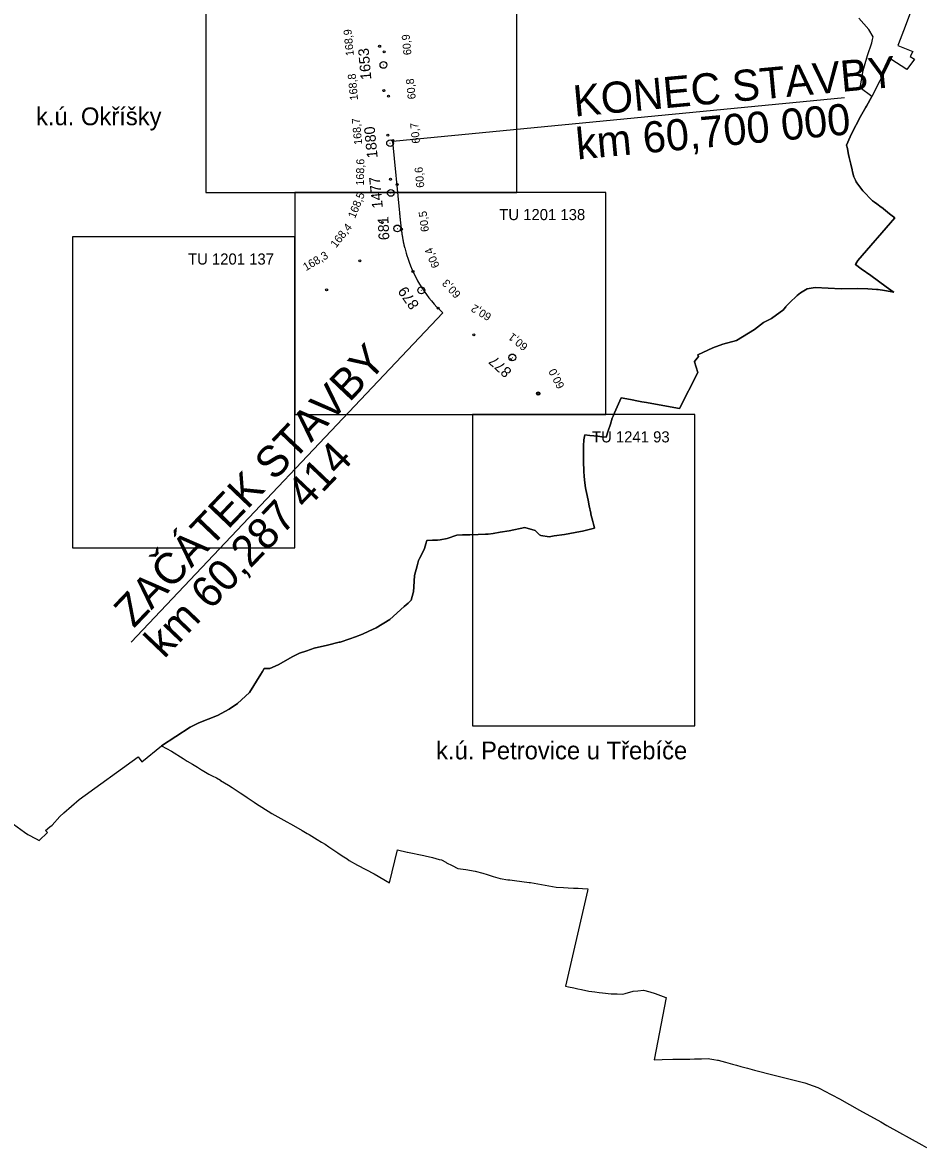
# Model space of a CAD drawing. Extents: x -661028 to -488604, y -1150850 to -1117549.
# Drawn here: x -659612 to -657588, y -1150849 to -1148318 of the extents above; entities that cross this region are included whole.
import ezdxf

# ---------------------------------------------------------------- set-up
doc = ezdxf.new("R2010")
doc.units = 0
for name, color, linetype in [('Polygon ku', 7, 'Continuous'), ('Pop  PČ popisy', 7, 'Continuous'), ('Ramecky', 7, 'Continuous'), ('Vrstva 7', 7, 'Continuous'), ('Značky bodu BP', 7, 'Continuous'), ('ŽBP', 7, 'Continuous')]:
    doc.layers.add(name, color=color, linetype=linetype)

msp = doc.modelspace()

# ---------------------------------------------------------------- linework, layer by layer
at = {"layer": 'Polygon ku'}
for points in [[(-657576.5, -1148192.9), (-657630.8, -1148336.7), (-657641.9, -1148366), (-657643.3, -1148369.6), (-657609.7, -1148383.3), (-657615.4, -1148394.8), (-657605.9, -1148400.4), (-657623, -1148423.5), (-657659.5, -1148400.5), (-657661.2, -1148404), (-657665.6, -1148413.6), (-657702.1, -1148484.7), (-657714, -1148506.4), (-657715.2, -1148508.4), (-657727.1, -1148529.4), (-657747.4, -1148568.7), (-657750.8, -1148575.3), (-657758.6, -1148593.8), (-657756.6, -1148601.7), (-657755.6, -1148607), (-657754.1, -1148614.6), (-657752.7, -1148621.8), (-657749.3, -1148636.7), (-657746.3, -1148649.5), (-657745.3, -1148654.1), (-657742.8, -1148664.9), (-657739, -1148672.4), (-657736.9, -1148676.7), (-657735.6, -1148678.9), (-657721.9, -1148696.4), (-657700.4, -1148719), (-657696.2, -1148722.1), (-657690.6, -1148726.1), (-657681, -1148733), (-657679.5, -1148734), (-657676.6, -1148736.4), (-657675.4, -1148737.3), (-657671.3, -1148740.6), (-657662.1, -1148748), (-657656.3, -1148752.8), (-657650.4, -1148757.5), (-657733.3, -1148853.6), (-657735.7, -1148856.8), (-657738.3, -1148860.6), (-657739, -1148861.8), (-657738.4, -1148862.3), (-657725.8, -1148871.9), (-657704.1, -1148887.4), (-657669.5, -1148912.2), (-657659, -1148919.7), (-657652.8, -1148924.8), (-657673.3, -1148921.1), (-657687.8, -1148918.5), (-657691.2, -1148918.3), (-657711.3, -1148917.4), (-657733.4, -1148916.4), (-657770.7, -1148916.9), (-657829.3, -1148913.9), (-657847.4, -1148917.4), (-657862.2, -1148925.7), (-657869.7, -1148931.8), (-657887, -1148948.8), (-657891.3, -1148953), (-657895.2, -1148956.8), (-657895.6, -1148957.3), (-657899.5, -1148962.5), (-657900.2, -1148963.5), (-657927.6, -1148984), (-657945.9, -1148992.9), (-657965.7, -1149008.8), (-658006.1, -1149033.2), (-658036.8, -1149041.4), (-658059.4, -1149049.8), (-658093.4, -1149065.5), (-658091.5, -1149069.6), (-658101, -1149080.2), (-658100.7, -1149081.3), (-658093, -1149105.1), (-658134.7, -1149186.5), (-658155.6, -1149182.6), (-658175.8, -1149178.9), (-658196.5, -1149175.1), (-658209, -1149172.8), (-658218.9, -1149170.9), (-658230.4, -1149168.8), (-658240.9, -1149166.9), (-658252.7, -1149164.7), (-658265.7, -1149162.3), (-658280.6, -1149195.8), (-658283.8, -1149203.2), (-658285.6, -1149208.3), (-658289.9, -1149221.3), (-658295.1, -1149236.5), (-658299.8, -1149250.7), (-658309.5, -1149249.6), (-658318.1, -1149248.7), (-658327, -1149247.7), (-658336.4, -1149246.7), (-658347.4, -1149245.5), (-658350, -1149256.9), (-658350.1, -1149270.3), (-658350.2, -1149274), (-658350.4, -1149293.6), (-658350.5, -1149304.8), (-658349.4, -1149328.3), (-658348.9, -1149338.6), (-658348.8, -1149339.1), (-658347.1, -1149353.2), (-658345.8, -1149364.4), (-658345.3, -1149368.6), (-658343.9, -1149375.4), (-658340.3, -1149392.6), (-658337.6, -1149405.5), (-658334.3, -1149421.5), (-658333.8, -1149423.9), (-658329.4, -1149440.5), (-658327.7, -1149446.6), (-658326.3, -1149451.9), (-658325.4, -1149455.3), (-658352.6, -1149461.9), (-658357.5, -1149463.1), (-658393.3, -1149469.6), (-658416.2, -1149473), (-658427.9, -1149474.8), (-658446.3, -1149471.6), (-658449.6, -1149470.2), (-658455.7, -1149464.3), (-658459.4, -1149460.8), (-658482.5, -1149453.9), (-658517.9, -1149461.1), (-658537.7, -1149464.5), (-658553.8, -1149467.2), (-658565.1, -1149468.6), (-658571.2, -1149468.8), (-658587.6, -1149469.4), (-658606.4, -1149470.1), (-658622.8, -1149470.7), (-658635.2, -1149471.2), (-658657.4, -1149478.9), (-658672.5, -1149481.3), (-658678.6, -1149482.3), (-658690.2, -1149482.5), (-658702.7, -1149482.8), (-658704.7, -1149490.4), (-658707.7, -1149501.1), (-658712.8, -1149511.1), (-658719, -1149523.3), (-658721.4, -1149527.8), (-658724.6, -1149540.2), (-658730.2, -1149561.8), (-658731.9, -1149587.5), (-658732.6, -1149598.3), (-658733.3, -1149601.1), (-658735.5, -1149609.2), (-658737.7, -1149617.4), (-658742.4, -1149621.6), (-658744.9, -1149623.9), (-658753.4, -1149631.5), (-658785.8, -1149660.5), (-658816.8, -1149679.7), (-658833, -1149687.3), (-658847.6, -1149694.1), (-658862.9, -1149699.5), (-658876, -1149704.1), (-658878.5, -1149704.9), (-658895.6, -1149710.9), (-658898, -1149711.8), (-658899.9, -1149712.2), (-658926.3, -1149718.6), (-658956.1, -1149725.7), (-658973, -1149731.2), (-658989, -1149736.5), (-659005.7, -1149744.9), (-659035.7, -1149762.3), (-659050.7, -1149768.8), (-659055.6, -1149771), (-659068.6, -1149770.9), (-659072.6, -1149778.1), (-659075.8, -1149784.1), (-659101.6, -1149824.7), (-659128.3, -1149849.9), (-659147.4, -1149862.7), (-659173.9, -1149877.1), (-659215.5, -1149893.2), (-659216.8, -1149893.7), (-659234.9, -1149903.1), (-659299.6, -1149945.1), (-659277.3, -1149957.1), (-659250.9, -1149973.4), (-659241.5, -1149979.2), (-659230.1, -1149986.2), (-659218.5, -1149993.3), (-659209.6, -1149998.7), (-659208.4, -1149999.4), (-659192.7, -1150008.4), (-659185.3, -1150012.4), (-659176.2, -1150017.2), (-659167.2, -1150022.4), (-659166.6, -1150022.8), (-659158.2, -1150028), (-659149, -1150033.7), (-659140.6, -1150038.9), (-659122.8, -1150050.4), (-659110.1, -1150059), (-659107, -1150061.1), (-659091.4, -1150071.8), (-659088, -1150074), (-659051.2, -1150096.9), (-659038.2, -1150105), (-659024.2, -1150112.4), (-659002.7, -1150123.9), (-658983.5, -1150135.3), (-658972.2, -1150141.9), (-658967.3, -1150144.8), (-658961.6, -1150148.4), (-658949.2, -1150156.1), (-658939.9, -1150161.6), (-658931.8, -1150166.4), (-658923, -1150172.3), (-658903.3, -1150185.5), (-658893.2, -1150192.2), (-658882.1, -1150199.5), (-658877.3, -1150202.7), (-658859, -1150213.3), (-658821, -1150233), (-658787.1, -1150253.3), (-658768.4, -1150178.8), (-658746.7, -1150183.9), (-658746.2, -1150184), (-658709.3, -1150191.5), (-658706.3, -1150192.3), (-658690.2, -1150196.5), (-658674.9, -1150200.5), (-658670.1, -1150201.8), (-658660, -1150206.9), (-658658.2, -1150207.9), (-658645.7, -1150214.1), (-658632.8, -1150220.6), (-658615.2, -1150223.4), (-658594.2, -1150226.6), (-658577.1, -1150231.2), (-658567.3, -1150234.3), (-658558.4, -1150237.1), (-658553.4, -1150238.7), (-658537.7, -1150243.8), (-658520.7, -1150246.1), (-658516.2, -1150246.7), (-658505.4, -1150248), (-658489, -1150250.1), (-658472.3, -1150252.1), (-658469.5, -1150252.5), (-658412, -1150263.3), (-658395.5, -1150264), (-658384.6, -1150264.5), (-658373.2, -1150265), (-658362.4, -1150265.4), (-658352.8, -1150265.9), (-658340.6, -1150266.4), (-658341.7, -1150271.4), (-658391, -1150485.6), (-658384.4, -1150487), (-658371.9, -1150489.7), (-658362.9, -1150491.7), (-658355.2, -1150493.3), (-658338.6, -1150496.9), (-658324.9, -1150498.6), (-658314.9, -1150499.8), (-658307.6, -1150500.6), (-658287.9, -1150502.6), (-658274.4, -1150503.2), (-658262.5, -1150503.8), (-658256.5, -1150502.1), (-658238.4, -1150497.2), (-658228.2, -1150496), (-658215.8, -1150494.5), (-658201.2, -1150498.6), (-658189.3, -1150502), (-658183.6, -1150504.1), (-658165.5, -1150510.9), (-658164.2, -1150511.4), (-658191.6, -1150651), (-658173.4, -1150650.6), (-658149.3, -1150650.2), (-658145.1, -1150650.1), (-658118, -1150649.6), (-658111.5, -1150649.5), (-658100.5, -1150649.2), (-658098.2, -1150649.2), (-658084.8, -1150648.9), (-658069.6, -1150648.7), (-658066.1, -1150649.1), (-658057.3, -1150650.3), (-658049.4, -1150651.8), (-658047.7, -1150652.3), (-658031, -1150656.8), (-658015.2, -1150661), (-658006.2, -1150663.4), (-657996.3, -1150666.1), (-657981.6, -1150670), (-657965.5, -1150674.4), (-657921.9, -1150686.1), (-657853, -1150702.8), (-657834.2, -1150709.6), (-657823.4, -1150713.8), (-657817.3, -1150716.6), (-657809, -1150721.3), (-657774.5, -1150739.2), (-657729.7, -1150764.3), (-657682, -1150791), (-657668.2, -1150798.7), (-657589.5, -1150842.6), (-657579, -1150848.5)], [(-659632.5, -1150121.5), (-659607.3, -1150139.4), (-659599.8, -1150144.7), (-659581.1, -1150154.6), (-659574.4, -1150158.1), (-659555.9, -1150140), (-659560.1, -1150135.4), (-659550.8, -1150127.6), (-659545.7, -1150123.5), (-659528.3, -1150103.9), (-659519.2, -1150095.5), (-659484.9, -1150066), (-659351.8, -1149969.8), (-659344, -1149980.7), (-659299.6, -1149945.1), (-659234.9, -1149903.1), (-659216.8, -1149893.7), (-659215.5, -1149893.2), (-659173.9, -1149877.1), (-659147.4, -1149862.7), (-659128.3, -1149849.9), (-659101.6, -1149824.7), (-659075.8, -1149784.1), (-659072.6, -1149778.1), (-659068.6, -1149770.9), (-659055.6, -1149771), (-659050.7, -1149768.8), (-659035.7, -1149762.3), (-659005.7, -1149744.9), (-658989, -1149736.5), (-658973, -1149731.2), (-658956.1, -1149725.7), (-658926.3, -1149718.6), (-658899.9, -1149712.2), (-658898, -1149711.8), (-658895.6, -1149710.9), (-658878.5, -1149704.9), (-658876, -1149704.1), (-658862.9, -1149699.5), (-658847.6, -1149694.1), (-658833, -1149687.3), (-658816.8, -1149679.7), (-658785.8, -1149660.5), (-658753.4, -1149631.5), (-658744.9, -1149623.9), (-658742.4, -1149621.6), (-658737.7, -1149617.4), (-658735.5, -1149609.2), (-658733.3, -1149601.1), (-658732.6, -1149598.3), (-658731.9, -1149587.5), (-658730.2, -1149561.8), (-658724.6, -1149540.2), (-658721.4, -1149527.8), (-658719, -1149523.3), (-658712.8, -1149511.1), (-658707.7, -1149501.1), (-658704.7, -1149490.4), (-658702.7, -1149482.8), (-658690.2, -1149482.5), (-658678.6, -1149482.3), (-658672.5, -1149481.3), (-658657.4, -1149478.9), (-658635.2, -1149471.2), (-658622.8, -1149470.7), (-658606.4, -1149470.1), (-658587.6, -1149469.4), (-658571.2, -1149468.8), (-658565.1, -1149468.6), (-658553.8, -1149467.2), (-658537.7, -1149464.5), (-658517.9, -1149461.1), (-658482.5, -1149453.9), (-658459.4, -1149460.8), (-658455.7, -1149464.3), (-658449.6, -1149470.2), (-658446.3, -1149471.6), (-658427.9, -1149474.8), (-658416.2, -1149473), (-658393.3, -1149469.6), (-658357.5, -1149463.1), (-658352.6, -1149461.9), (-658325.4, -1149455.3), (-658326.3, -1149451.9), (-658327.7, -1149446.6), (-658329.4, -1149440.5), (-658333.8, -1149423.9), (-658334.3, -1149421.5), (-658337.6, -1149405.5), (-658340.3, -1149392.6), (-658343.9, -1149375.4), (-658345.3, -1149368.6), (-658345.8, -1149364.4), (-658347.1, -1149353.2), (-658348.8, -1149339.1), (-658348.9, -1149338.6), (-658349.4, -1149328.3), (-658350.5, -1149304.8), (-658350.4, -1149293.6), (-658350.2, -1149274), (-658350.1, -1149270.3), (-658350, -1149256.9), (-658347.4, -1149245.5), (-658336.4, -1149246.7), (-658327, -1149247.7), (-658318.1, -1149248.7), (-658309.5, -1149249.6), (-658299.8, -1149250.7), (-658295.1, -1149236.5), (-658289.9, -1149221.3), (-658285.6, -1149208.3), (-658283.8, -1149203.2), (-658280.6, -1149195.8), (-658265.7, -1149162.3), (-658252.7, -1149164.7), (-658240.9, -1149166.9), (-658230.4, -1149168.8), (-658218.9, -1149170.9), (-658209, -1149172.8), (-658196.5, -1149175.1), (-658175.8, -1149178.9), (-658155.6, -1149182.6), (-658134.7, -1149186.5), (-658093, -1149105.1), (-658100.7, -1149081.3), (-658101, -1149080.2), (-658091.5, -1149069.6), (-658093.4, -1149065.5), (-658059.4, -1149049.8), (-658036.8, -1149041.4), (-658006.1, -1149033.2), (-657965.7, -1149008.8), (-657945.9, -1148992.9), (-657927.6, -1148984), (-657900.2, -1148963.5), (-657899.5, -1148962.5), (-657895.6, -1148957.3), (-657895.2, -1148956.8), (-657891.3, -1148953), (-657887, -1148948.8), (-657869.7, -1148931.8), (-657862.2, -1148925.7), (-657847.4, -1148917.4), (-657829.3, -1148913.9), (-657770.7, -1148916.9), (-657733.4, -1148916.4), (-657711.3, -1148917.4), (-657691.2, -1148918.3), (-657687.8, -1148918.5), (-657673.3, -1148921.1), (-657652.8, -1148924.8), (-657659, -1148919.7), (-657669.5, -1148912.2), (-657704.1, -1148887.4), (-657725.8, -1148871.9), (-657738.4, -1148862.3), (-657739, -1148861.8), (-657738.3, -1148860.6), (-657735.7, -1148856.8), (-657733.3, -1148853.6), (-657650.4, -1148757.5), (-657656.3, -1148752.8), (-657662.1, -1148748), (-657671.3, -1148740.6), (-657675.4, -1148737.3), (-657676.6, -1148736.4), (-657679.5, -1148734), (-657681, -1148733), (-657690.6, -1148726.1), (-657696.2, -1148722.1), (-657700.4, -1148719), (-657721.9, -1148696.4), (-657735.6, -1148678.9), (-657736.9, -1148676.7), (-657739, -1148672.4), (-657742.8, -1148664.9), (-657745.3, -1148654.1), (-657746.3, -1148649.5), (-657749.3, -1148636.7), (-657752.7, -1148621.8), (-657754.1, -1148614.6), (-657755.6, -1148607), (-657756.6, -1148601.7), (-657758.6, -1148593.8), (-657750.8, -1148575.3), (-657747.4, -1148568.7), (-657727.1, -1148529.4), (-657715.2, -1148508.4), (-657714, -1148506.4), (-657702.1, -1148484.7), (-657728.4, -1148464.7), (-657721.4, -1148425.7), (-657718.4, -1148415.5), (-657711.5, -1148392.2), (-657702, -1148363.5), (-657700.4, -1148356.4), (-657699.2, -1148350.4), (-657708.7, -1148333.7), (-657731, -1148308.1)]]:
    msp.add_lwpolyline(points, dxfattribs=at)
at = {"layer": 'Pop  PČ popisy'}
for p, q in [((-657763.6, -1148487.2), (-658779.1, -1148585.7)), ((-659368.1, -1149712.2), (-658666.9, -1148971))]:
    msp.add_line(p, q, dxfattribs=at)
at = {"layer": 'Ramecky'}
for points in [[(-659200, -1148700), (-658500, -1148700), (-658500, -1148200), (-659200, -1148200)], [(-659000, -1149200), (-658300, -1149200), (-658300, -1148700), (-659000, -1148700)], [(-659500, -1149500), (-659000, -1149500), (-659000, -1148800), (-659500, -1148800)], [(-658600, -1149900), (-658100, -1149900), (-658100, -1149200), (-658600, -1149200)]]:
    msp.add_lwpolyline(points, close=True, dxfattribs=at)
at = {"layer": 'Vrstva 7'}
for centre, radius in [((-658808.9, -1148371.5), 2.25), ((-658808.9, -1148371.5), 2.25), ((-658798.7, -1148384.2), 2.25), ((-658798.7, -1148384.2), 2.25), ((-658799.6, -1148471.3), 2.25), ((-658799.6, -1148471.3), 2.25), ((-658789, -1148483.7), 2.25), ((-658789, -1148483.7), 2.25), ((-658790.3, -1148571.2), 2.25), ((-658790.3, -1148571.2), 2.25), ((-658779.3, -1148583.2), 2.25), ((-658779.3, -1148583.2), 2.25), ((-658784.5, -1148670.7), 2.25), ((-658784.5, -1148670.7), 2.25), ((-658769.7, -1148682.7), 2.25), ((-658769.7, -1148682.7), 2.25), ((-658803.4, -1148768.2), 2.25), ((-658803.4, -1148768.2), 2.25), ((-658759.6, -1148782.8), 2.25), ((-658759.6, -1148782.8), 2.25), ((-658853.2, -1148854.1), 2.25), ((-658853.2, -1148854.1), 2.25), ((-658733.9, -1148878.2), 2.25), ((-658733.9, -1148878.2), 2.25), ((-658928.1, -1148919.1), 2.25), ((-658928.1, -1148919.1), 2.25), ((-658677.5, -1148960.6), 2.25), ((-658677.5, -1148960.6), 2.25), ((-658597.1, -1149020.7), 2.25), ((-658597.1, -1149020.7), 2.25), ((-658514.8, -1149075.8), 2.25), ((-658514.8, -1149075.8), 2.25), ((-658452.1, -1149152.7), 3.74), ((-658452.1, -1149152.7), 3.74), ((-658452.1, -1149152.7), 2.26), ((-658452.1, -1149152.7), 2.26)]:
    msp.add_circle(centre, radius, dxfattribs=at)
at = {"layer": 'Značky bodu BP'}
msp.add_line((-658763.5, -1148746.4), (-658779.1, -1148585.7), dxfattribs=at)
for points in [[(-658755.8, -1148808), (-658756, -1148807.1), (-658756.2, -1148806.1), (-658756.3, -1148805.2), (-658756.5, -1148804.2), (-658756.7, -1148803.2), (-658756.8, -1148802.2), (-658757, -1148801.3), (-658757.1, -1148800.3), (-658757.3, -1148799.3), (-658757.5, -1148798.3), (-658757.6, -1148797.4), (-658757.8, -1148796.4), (-658757.9, -1148795.4), (-658758.1, -1148794.4), (-658758.2, -1148793.5), (-658758.3, -1148792.5), (-658758.5, -1148791.5), (-658758.6, -1148790.5), (-658758.8, -1148789.6), (-658758.9, -1148788.6), (-658759, -1148787.6), (-658759.2, -1148786.6), (-658759.3, -1148785.6), (-658759.4, -1148784.7), (-658759.5, -1148783.7), (-658759.7, -1148782.7), (-658759.8, -1148781.7), (-658759.9, -1148780.7), (-658760, -1148779.8), (-658760.1, -1148778.8), (-658760.3, -1148777.8), (-658760.4, -1148776.8), (-658760.5, -1148775.8), (-658760.6, -1148774.9), (-658760.7, -1148773.9), (-658760.8, -1148772.9), (-658760.9, -1148771.9), (-658761, -1148770.9), (-658761.2, -1148770), (-658761.3, -1148769), (-658761.4, -1148768), (-658761.5, -1148767), (-658761.6, -1148766), (-658761.7, -1148765), (-658761.8, -1148764.1), (-658761.9, -1148763.1), (-658762, -1148762.1), (-658762.1, -1148761.1), (-658762.2, -1148760.1), (-658762.3, -1148759.1), (-658762.4, -1148758.2), (-658762.5, -1148757.2), (-658762.6, -1148756.2), (-658762.7, -1148755.2), (-658762.8, -1148754.2), (-658762.9, -1148753.3), (-658763, -1148752.3), (-658763.1, -1148751.3), (-658763.2, -1148750.3), (-658763.3, -1148749.3), (-658763.3, -1148748.3), (-658763.4, -1148747.4), (-658763.5, -1148746.4)], [(-658752.4, -1148824.5), (-658752.6, -1148823.6), (-658752.8, -1148822.6), (-658753, -1148821.6), (-658753.3, -1148820.7), (-658753.5, -1148819.7), (-658753.7, -1148818.7), (-658753.9, -1148817.8), (-658754.1, -1148816.8), (-658754.3, -1148815.8), (-658754.5, -1148814.9), (-658754.7, -1148813.9), (-658754.9, -1148812.9), (-658755.1, -1148812), (-658755.3, -1148811), (-658755.4, -1148810), (-658755.6, -1148809.1), (-658755.8, -1148808)]]:
    msp.add_lwpolyline(points, dxfattribs=at)
msp.add_circle((-658763.5, -1148746.4), 0.375, dxfattribs=at)
for start, end in [(193.3174, 198.1805), (198.1805, 227.2085)]:
    msp.add_arc((-658469.2, -1148757.5), 291, start, end, dxfattribs=at)
at = {"layer": 'ŽBP'}
for p, q in [((-658800.9, -1148413.6), (-658799.9, -1148413.5)), ((-658785.9, -1148589.4), (-658784.9, -1148589.3)), ((-658784.4, -1148701.4), (-658783.4, -1148701.3)), ((-658769.6, -1148781.1), (-658768.6, -1148781.1)), ((-658715.6, -1148920.5), (-658714.6, -1148920.4)), ((-658511, -1149071.4), (-658510, -1149071.3))]:
    msp.add_line(p, q, dxfattribs=at)
for centre in [(-658800.4, -1148413.5), (-658785.4, -1148589.3), (-658783.9, -1148701.3), (-658769.1, -1148781.1), (-658715.1, -1148920.4), (-658510.5, -1149071.3)]:
    msp.add_circle(centre, 7.56, dxfattribs=at)

# ---------------------------------------------------------------- texts
at = {"layer": 'Polygon ku'}
for s, p in [('k.ú. Okříšky', (-659581.8, -1148549)), ('k.ú. Petrovice u Třebíče', (-658682, -1149975.4))]:
    msp.add_text(s, height=40, dxfattribs=at).set_placement(p)
at = {"layer": 'Pop  PČ popisy'}
for s, rotation, p in [('KONEC STAVBY', 5.2957, (-658370.5, -1148529.8)), ('km 60,700 000', 5.2957, (-658364.2, -1148626.3)), ('ZAČÁTEK STAVBY', 46.3395, (-659361.8, -1149681.9)), ('km 60,287 414', 46.3395, (-659293.6, -1149750.6))]:
    msp.add_text(s, height=70, rotation=rotation, dxfattribs=at).set_placement(p)
at = {"layer": 'Ramecky'}
for s, p in [('TU 1201 138', (-658539.9, -1148762.5)), ('TU 1201 137', (-659239.9, -1148862.5)), ('TU 1241 93', (-658331.4, -1149262.5))]:
    msp.add_text(s, height=25, dxfattribs=at).set_placement(p)
at = {"layer": 'Vrstva 7'}
for s, rotation, p in [('168,9', 95.3815, (-658866.8, -1148392.4)), ('168,9', 95.3815, (-658866.8, -1148392.4)), ('60,9', 95.4933, (-658737.2, -1148390.4)), ('60,9', 95.4933, (-658737.2, -1148390.4)), ('168,8', 95.3124, (-658857.4, -1148492.2)), ('168,8', 95.3124, (-658857.4, -1148492.2)), ('60,8', 95.5593, (-658727.6, -1148489.8)), ('60,8', 95.5593, (-658727.6, -1148489.8)), ('168,7', 95.3124, (-658848.1, -1148592.2)), ('168,7', 95.3124, (-658848.1, -1148592.2)), ('60,7', 95.5413, (-658718, -1148589.4)), ('60,7', 95.5413, (-658718, -1148589.4)), ('168,6', 88.8183, (-658844.4, -1148684.9)), ('168,6', 88.8183, (-658844.4, -1148684.9)), ('60,6', 95.5352, (-658708.2, -1148688.8)), ('60,6', 95.5352, (-658708.2, -1148688.8)), ('168,5', 67.8399, (-658864.4, -1148760)), ('168,5', 67.8399, (-658864.4, -1148760)), ('60,5', 96.7293, (-658698, -1148787.8)), ('60,5', 96.7293, (-658698, -1148787.8)), ('168,4', 51.9598, (-658907, -1148826.3)), ('168,4', 51.9598, (-658907, -1148826.3)), ('60,4', 112.9833, (-658673.6, -1148865.7)), ('60,4', 112.9833, (-658673.6, -1148865.7)), ('168,3', 30.4508, (-658974.7, -1148877.5)), ('168,3', 30.4508, (-658974.7, -1148877.5)), ('60,3', 132.933, (-658625, -1148928.2)), ('60,3', 132.933, (-658625, -1148928.2)), ('60,2', 149.304, (-658555.8, -1148974.9)), ('60,2', 149.304, (-658555.8, -1148974.9)), ('60,1', 141.2092, (-658473.9, -1149044.1)), ('60,1', 141.2092, (-658473.9, -1149044.1)), ('60,0', 117.3352, (-658392.5, -1149136)), ('60,0', 117.3352, (-658392.5, -1149136))]:
    msp.add_text(s, height=18, rotation=rotation, dxfattribs=at).set_placement(p)
at = {"layer": 'ŽBP'}
for s, rotation, p in [('1653', 95.0939, (-658827.4, -1148445.9)), ('1880', 95.8046, (-658813.2, -1148621.9)), ('1477', 95.9777, (-658801.5, -1148734.9)), ('681', 92.6497, (-658787, -1148807)), ('879', 125.1196, (-658718.9, -1148952.9)), ('877', 137.8168, (-658510, -1149101.4))]:
    msp.add_text(s, height=24, rotation=rotation, dxfattribs=at).set_placement(p)

doc.saveas('drawing.dxf')
